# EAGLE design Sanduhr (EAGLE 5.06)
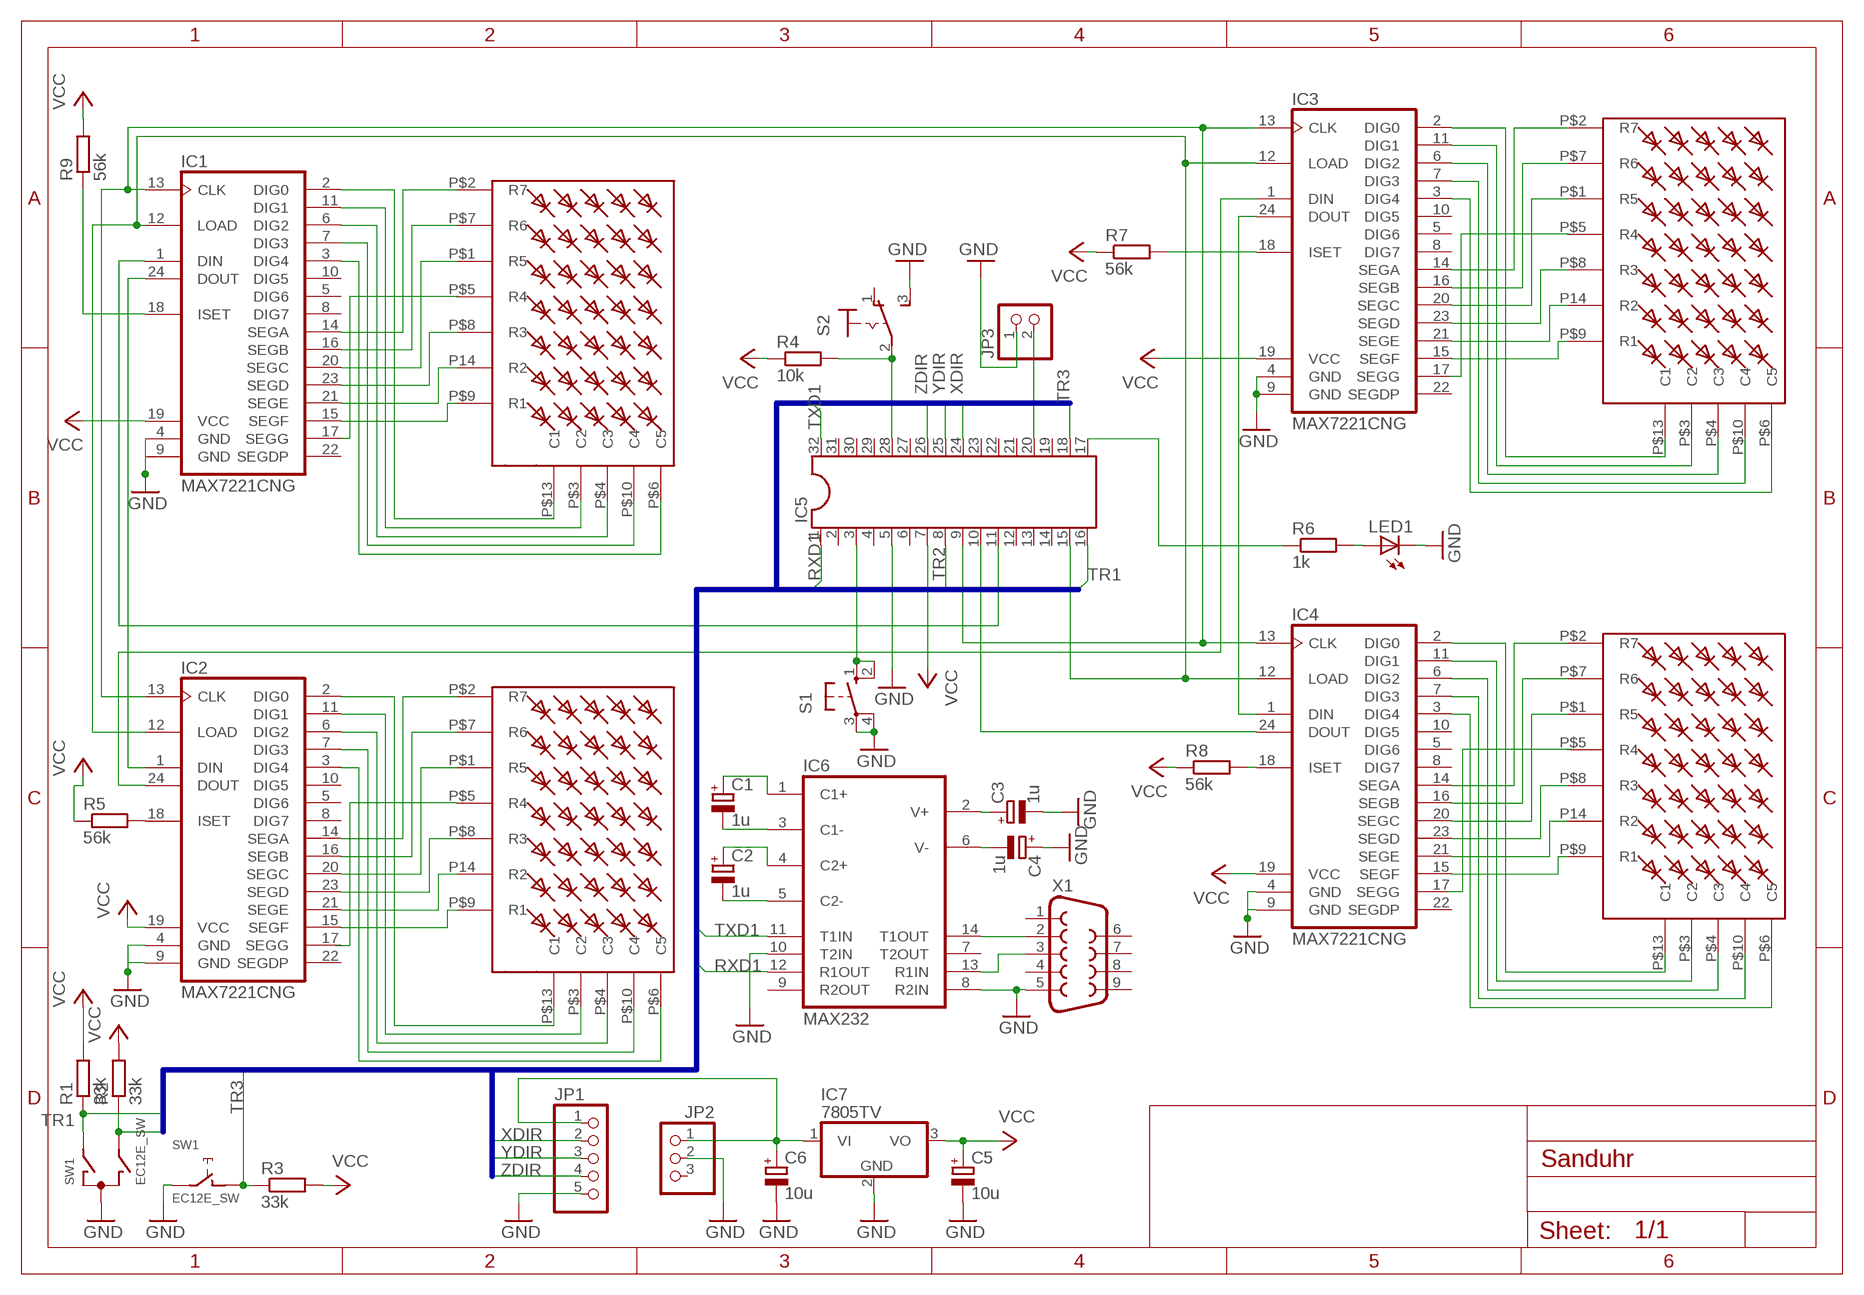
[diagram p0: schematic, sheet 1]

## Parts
C1  1u  CPOL-EUE2,5-6E  [E2,5-6E]
C2  1u  CPOL-EUE2,5-6E  [E2,5-6E]
C3  1u  CPOL-EUE2,5-6E  [E2,5-6E]
C4  1u  CPOL-EUE2,5-6E  [E2,5-6E]
C5  10u  CPOL-EUE2,5-6E  [E2,5-6E]
C6  10u  CPOL-EUE2,5-6E  [E2,5-6E]
IC1  MAX7221CNG  MAX7219CNG  [DIL24-3]
IC2  MAX7221CNG  MAX7219CNG  [DIL24-3]
IC3  MAX7221CNG  MAX7219CNG  [DIL24-3]
IC4  MAX7221CNG  MAX7219CNG  [DIL24-3]
IC5  DIL32  [DIL32]
IC6  MAX232  [DIL16]
IC7  7805TV  [TO220V]
JP1  PINHD-1X5  [1X05]
JP2  PINHD-1X3  [1X03]
JP3  PINHD-1X2  [1X02]
LED1  LED3MM  [LED3MM]
R1  33k  R-EU_0207/2V  [0207/2V]
R2  33k  R-EU_0207/2V  [0207/2V]
R3  33k  R-EU_0207/2V  [0207/2V]
R4  10k  R-EU_0207/2V  [0207/2V]
R5  56k  R-EU_0207/2V  [0207/2V]
R6  1k  R-EU_0207/2V  [0207/2V]
R7  56k  R-EU_0207/2V  [0207/2V]
R8  56k  R-EU_0207/2V  [0207/2V]
R9  56k  R-EU_0207/2V  [0207/2V]
S1  10-XX  [B3F-10XX]
S2  M9040P  [M9040P]
SW1  EC12E_SW  [ALPS_EC12E_SW]
U$1  TC20-11HWA  [P_SA20-11]
U$2  TC20-11HWA  [P_SA20-11]
U$3  TC20-11HWA  [P_SA20-11]
U$4  TC20-11HWA  [P_SA20-11]
X1  F09V  [F09V]

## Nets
GND: C3.- C4.+ C5.- C6.- IC1.4(GND) IC1.9(GND) IC2.4(GND) IC2.9(GND) IC3.4(GND) IC3.9(GND) IC4.4(GND) IC4.9(GND) IC5.5 IC6.8(R2IN) IC6.10(T2IN) IC7.2(GND) JP1.5 JP2.2 JP3.1 LED1.K(C) S1.3(P) S1.4(P1) S2.3(S) SW1.C SW1.E X1.5
N$1: IC1.14(SEGA) U$1.P$2(R7)
N$2: IC1.16(SEGB) U$1.P$7(R6)
N$3: IC1.20(SEGC) U$1.P$1(R5)
N$4: IC1.23(SEGD) U$1.P$8(R3)
N$5: IC1.21(SEGE) U$1.P14(R2)
N$6: IC1.15(SEGF) U$1.P$9(R1)
N$7: IC1.2(DIG0) U$1.P$13(C1)
N$8: IC1.11(DIG1) U$1.P$3(C2)
N$9: IC1.6(DIG2) U$1.P$4(C3)
N$10: IC1.7(DIG3) U$1.P$10(C4)
N$11: IC1.3(DIG4) U$1.P$6(C5)
N$12: IC2.14(SEGA) U$2.P$2(R7)
N$13: IC2.16(SEGB) U$2.P$7(R6)
N$14: IC2.20(SEGC) U$2.P$1(R5)
N$15: IC2.23(SEGD) U$2.P$8(R3)
N$16: IC2.21(SEGE) U$2.P14(R2)
N$17: IC2.15(SEGF) U$2.P$9(R1)
N$18: IC2.2(DIG0) U$2.P$13(C1)
N$19: IC2.11(DIG1) U$2.P$3(C2)
N$20: IC2.6(DIG2) U$2.P$4(C3)
N$21: IC2.7(DIG3) U$2.P$10(C4)
N$22: IC2.3(DIG4) U$2.P$6(C5)
N$23: IC3.14(SEGA) U$3.P$2(R7)
N$24: IC3.16(SEGB) U$3.P$7(R6)
N$25: IC3.20(SEGC) U$3.P$1(R5)
N$26: IC3.23(SEGD) U$3.P$8(R3)
N$27: IC3.21(SEGE) U$3.P14(R2)
N$28: IC3.15(SEGF) U$3.P$9(R1)
N$29: IC3.2(DIG0) U$3.P$13(C1)
N$30: IC3.11(DIG1) U$3.P$3(C2)
N$31: IC3.6(DIG2) U$3.P$4(C3)
N$32: IC3.7(DIG3) U$3.P$10(C4)
N$33: IC3.3(DIG4) U$3.P$6(C5)
N$34: IC4.14(SEGA) U$4.P$2(R7)
N$35: IC4.16(SEGB) U$4.P$7(R6)
N$36: IC4.20(SEGC) U$4.P$1(R5)
N$37: IC4.23(SEGD) U$4.P$8(R3)
N$38: IC4.21(SEGE) U$4.P14(R2)
N$39: IC4.15(SEGF) U$4.P$9(R1)
N$40: IC4.2(DIG0) U$4.P$13(C1)
N$41: IC4.11(DIG1) U$4.P$3(C2)
N$42: IC4.6(DIG2) U$4.P$4(C3)
N$43: IC4.7(DIG3) U$4.P$10(C4)
N$44: IC4.3(DIG4) U$4.P$6(C5)
N$45: IC1.24(DOUT) IC2.1(DIN)
N$46: IC2.24(DOUT) IC3.1(DIN)
N$47: IC3.24(DOUT) IC4.1(DIN)
N$48: IC1.13(CLK) IC2.13(CLK) IC3.13(CLK) IC4.13(CLK) IC5.9
N$49: IC4.24(DOUT) IC5.10
N$50: IC1.1(DIN) IC5.11
N$51: IC1.12(LOAD) IC2.12(LOAD) IC3.12(LOAD) IC4.12(LOAD) IC5.15
N$52: IC5.28 R4.2 S2.2(P)
N$53: LED1.A R6.2
N$54: IC3.18(ISET) R7.2
N$55: C1.+ IC6.1(C1+)
N$56: C1.- IC6.3(C1-)
N$57: C2.+ IC6.4(C2+)
N$58: C2.- IC6.5(C2-)
N$59: C3.+ IC6.2(V+)
N$60: C4.- IC6.6(V-)
N$61: IC6.14(T1OUT) X1.2
N$62: IC6.13(R1IN) X1.3
N$63: C6.+ IC7.1(VI) JP1.1 JP2.1
N$64: IC2.18(ISET) R5.2
N$65: IC4.18(ISET) R8.2
N$66: IC1.18(ISET) R9.1
N$67: IC5.3 S1.1(S) S1.2(S1)
N$68: IC5.17 R6.1
N$69: IC5.20 JP3.2
N$70: IC1.17(SEGG)
N$71: U$2.P$5(R4)
RXD1: IC5.1 IC6.12(R1OUT)
TR1: IC5.16 R1.1 SW1.A
TR2: IC5.8 R2.1 SW1.B
TR3: IC5.18 R3.1 SW1.D
TXD1: IC5.32 IC6.11(T1IN)
VCC: C5.+ IC1.19(VCC) IC2.19(VCC) IC3.19(VCC) IC4.19(VCC) IC5.7 IC7.3(VO) R1.2 R2.2 R3.2 R4.1 R5.1 R7.1 R8.1 R9.2
XDIR: IC5.24 JP1.2
YDIR: IC5.25 JP1.3
ZDIR: IC5.26 JP1.4
Unconnected: IC1.5(DIG6) IC1.8(DIG7) IC1.10(DIG5) IC1.22(SEGDP) IC2.5(DIG6) IC2.8(DIG7) IC2.10(DIG5) IC2.17(SEGG) IC2.22(SEGDP) IC3.5(DIG6) IC3.8(DIG7) IC3.10(DIG5) IC3.17(SEGG) IC3.22(SEGDP) IC4.5(DIG6) IC4.8(DIG7) IC4.10(DIG5) IC4.17(SEGG) IC4.22(SEGDP) IC5.2 IC5.4 IC5.6 IC5.12 IC5.13 IC5.14 IC5.19 IC5.21 IC5.22 IC5.23 IC5.27 IC5.29 IC5.30 IC5.31 IC6.7(T2OUT) IC6.9(R2OUT) JP2.3 S2.1(O) SW1.GND1(G) SW1.GND2(G) U$1.P$5(R4) U$3.P$5(R4) U$4.P$5(R4) X1.1 X1.4 X1.6 X1.7 X1.8 X1.9

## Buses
BUS:RXD1,TXD1,TR1,TR2,TR3,XDIR,YDIR,ZDIR

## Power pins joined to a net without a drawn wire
GND: IC6.15(GND)
VCC: IC6.16(VCC)

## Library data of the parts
C1-C6 = rcl:CPOL-EU: POLARIZED CAPACITOR, European symbol
IC1-IC4 = maxim:MAX7219CNG: LED DISPLAY DRIVER
IC5 = ic-package:DIL32: Dual In Line
IC6 = maxim:MAX232: RS232 TRANSEIVER
IC7 = linear:78*: Positive VOLTAGE REGULATOR Source: http://cache.national.com/ds/LM/LM78L05.pdf http://www.fairchildsemi.com/ds/LM/LM7805.pdf
JP1 = pinhead:PINHD-1X5: PIN HEADER
JP2 = pinhead:PINHD-1X3: PIN HEADER
JP3 = pinhead:PINHD-1X2: PIN HEADER
LED1 = led:LED: LED
R1-R9 = rcl:R-EU_: RESISTOR, European symbol
S1 = switch-omron:10-XX: OMRON SWITCH
S2 = switch:M9040P: TOGGLE SWITCH Marquardt
SW1 = switch-alps:EC12E_SW: ALPS rotary Encoder EC12E series with switch
U$1-U$4 = display-kingbright-skl:TC20-11HWA: 50mm 5x7 DOT MATRIX DISPLAY
X1 = con-subd:F09: SUB-D

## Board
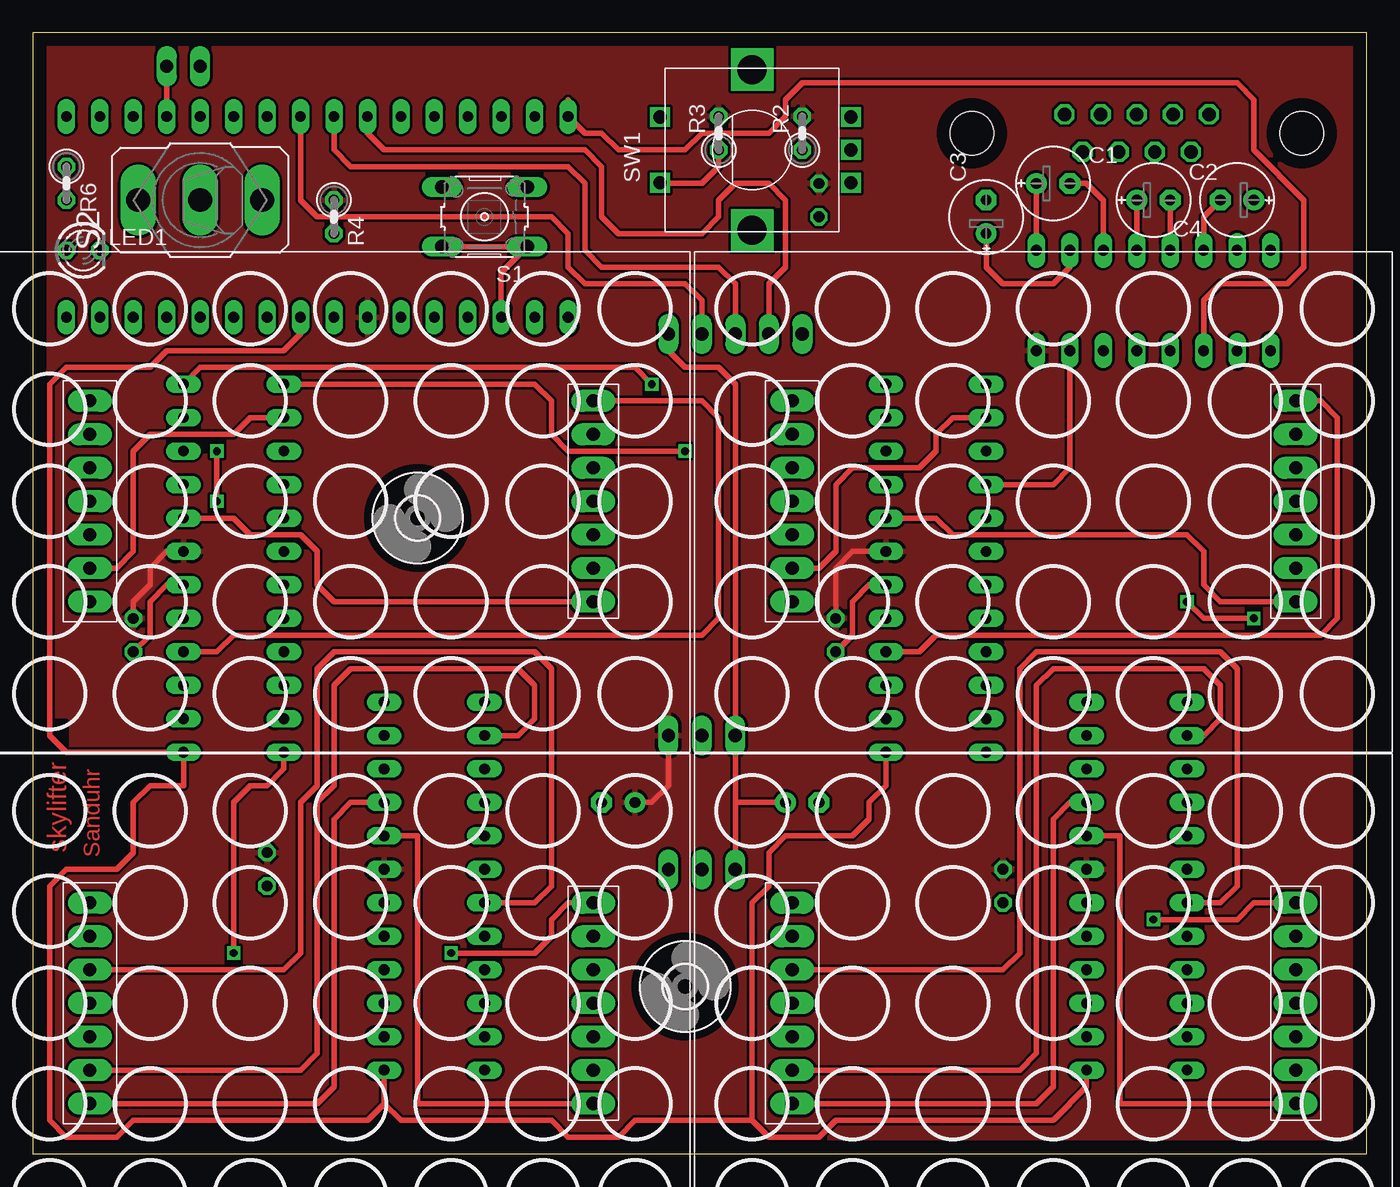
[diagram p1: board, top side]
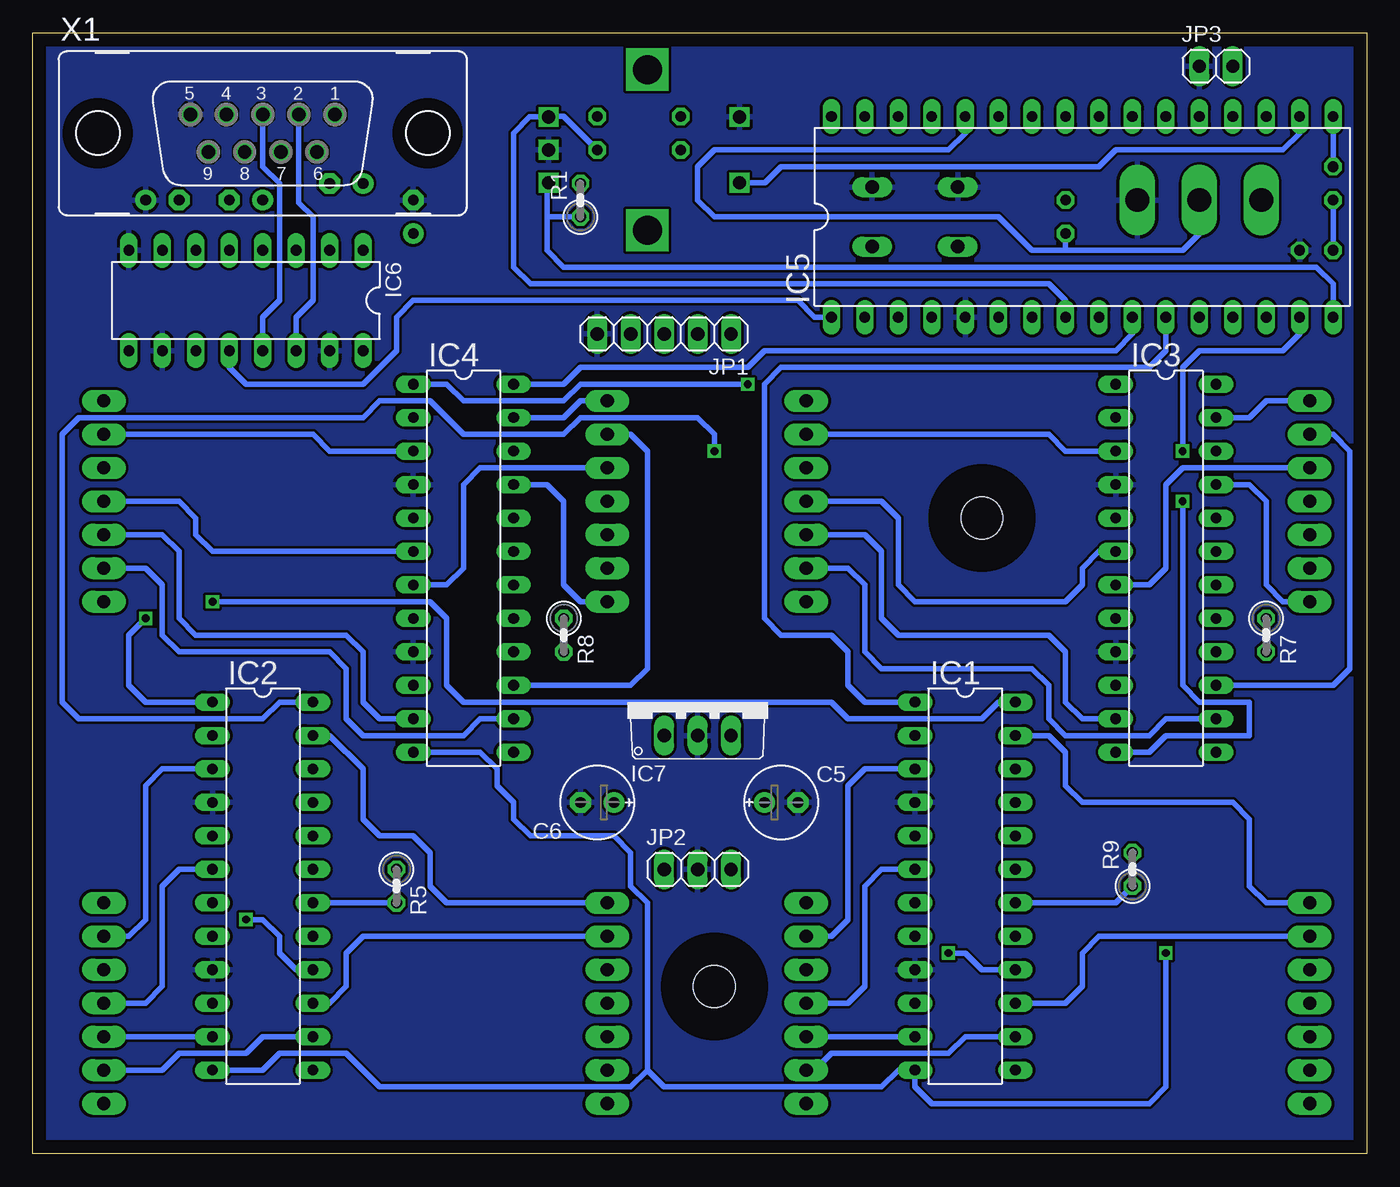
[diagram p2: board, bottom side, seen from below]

Size 101.27 x 85.08 mm. Coordinates in mm from the lower left corner, seen from the top.
Outline: 0,0 101.27,0 101.27,85.08 0,85.08 0,0
Copper layers (1*16): Top 0.035mm / dielectric 1.5mm / Bottom 0.035mm
Design rules "default": minimum track width 10mil, minimum drill 24mil, track to track 8mil, track to pad 8mil, pad to pad 8mil, via to via 8mil, smd to smd 8mil, copper to edge 40mil, drill to drill 8mil, minimum pad ring 10mil, minimum via ring 8mil, stop-mask expansion 4mil, vias tented up to drill 0mil, thermal gap 10mil

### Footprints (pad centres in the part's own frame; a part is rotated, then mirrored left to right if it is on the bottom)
E2,5-6E = drill 0.813 pad 1.575 round: + -1.27,0 | drill 0.813 pad 1.575 octagon: - 1.27,0
3,2 = hole 3.2: 0,0
DIL24-3 = drill 0.813 long: 1 -13.97,-3.81; 2 -11.43,-3.81; 3 -8.89,-3.81; 4 -6.35,-3.81; 5 -3.81,-3.81; 6 -1.27,-3.81; 7 1.27,-3.81; 8 3.81,-3.81; 9 6.35,-3.81; 10 8.89,-3.81; 11 11.43,-3.81; 12 13.97,-3.81; 13 13.97,3.81; 14 11.43,3.81; 15 8.89,3.81; 16 6.35,3.81; 17 3.81,3.81; 18 1.27,3.81; 19 -1.27,3.81; 20 -3.81,3.81; 21 -6.35,3.81; 22 -8.89,3.81; 23 -11.43,3.81; 24 -13.97,3.81
DIL32 = drill 0.813 long: 1 -19.05,-7.62; 2 -16.51,-7.62; 3 -13.97,-7.62; 4 -11.43,-7.62; 5 -8.89,-7.62; 6 -6.35,-7.62; 7 -3.81,-7.62; 8 -1.27,-7.62; 9 1.27,-7.62; 10 3.81,-7.62; 11 6.35,-7.62; 12 8.89,-7.62; 13 11.43,-7.62; 14 13.97,-7.62; 15 16.51,-7.62; 16 19.05,-7.62; 17 19.05,7.62; 18 16.51,7.62; 19 13.97,7.62; 20 11.43,7.62; 21 8.89,7.62; 22 6.35,7.62; 23 3.81,7.62; 24 1.27,7.62; 25 -1.27,7.62; 26 -3.81,7.62; 27 -6.35,7.62; 28 -8.89,7.62; 29 -11.43,7.62; 30 -13.97,7.62; 31 -16.51,7.62; 32 -19.05,7.62
DIL16 = drill 0.813 long: 1 -8.89,-3.81; 2 -6.35,-3.81; 3 -3.81,-3.81; 4 -1.27,-3.81; 5 1.27,-3.81; 6 3.81,-3.81; 7 6.35,-3.81; 8 8.89,-3.81; 9 8.89,3.81; 10 6.35,3.81; 11 3.81,3.81; 12 1.27,3.81; 13 -1.27,3.81; 14 -3.81,3.81; 15 -6.35,3.81; 16 -8.89,3.81
TO220V = drill 1.016 long: 1 -2.54,-2.54; 2 0,-2.54; 3 2.54,-2.54
1X05 = drill 1.016 long: 1 -5.08,0; 2 -2.54,0; 3 0,0; 4 2.54,0; 5 5.08,0
1X03 = drill 1.016 long: 1 -2.54,0; 2 0,0; 3 2.54,0
1X02 = drill 1.016 long: 1 -1.27,0; 2 1.27,0
LED3MM = drill 0.813 octagon: A -1.27,0; K 1.27,0
0207/2V = drill 0.813 octagon: 1 -1.27,0; 2 1.27,0
B3F-10XX = drill 1.016 long: 1 -3.251,2.261; 2 3.251,2.261; 3 -3.251,-2.261; 4 3.251,-2.261
M9040P = drill 1.803 long: 1 0,4.699; 2 0,0; 3 0,-4.699
ALPS_EC12E_SW = drill 1 square: A -2.5,-7.5; B 2.5,-7.5; C 0,-7.5; D -2.5,7; E 2.5,7 | drill 2.2 square: GND1 -6.1,0; GND2 6.1,0
P_SA20-11 = drill 1 pad 1.676 long: P14 -7.62,19.812; P$1 -7.62,-18.415; P$2 -5.08,-18.415; P$3 -2.54,-18.415; P$4 0,-18.415; P$5 2.54,-18.415; P$6 5.08,-18.415; P$7 7.62,-18.415; P$8 7.62,19.812; P$9 5.08,19.812; P$10 2.54,19.812; P$11 0,19.812; P$12 -2.54,19.812; P$13 -5.08,19.812
F09V = drill 1.016 octagon: 1 5.486,1.422; 2 2.743,1.422; 3 0,1.422; 4 -2.743,1.422; 5 -5.486,1.422; 6 4.115,-1.422; 7 1.372,-1.422; 8 -1.372,-1.422; 9 -4.115,-1.422 | hole 3.302: -12.522,0; 12.522,0

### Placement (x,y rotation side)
C1  77.47,73.66 0 top
C2  85.09,72.39 0 top
C3  72.39,71.12 90 top
C4  91.44,72.39 180 top
C5  44.45,26.67 0 bottom
C6  58.42,26.67 180 bottom
E$1  [3,2]  49.53,12.7 0 top
E$2  [3,2]  29.21,48.26 0 top
IC1  30.48,20.32 270 bottom
IC2  83.82,20.32 270 bottom
IC3  15.24,44.45 270 bottom
IC4  68.58,44.45 270 bottom
IC5  21.59,71.12 0 bottom
IC6  85.09,64.77 180 bottom
IC7  50.8,34.29 0 bottom
JP1  53.34,62.23 180 bottom
JP2  50.8,21.59 0 bottom
JP3  11.43,82.55 0 bottom
LED1  3.81,68.58 0 top
R1  59.69,72.39 90 bottom
R2  58.42,77.47 90 top
R3  52.07,77.47 90 top
R4  22.86,71.12 270 top
R5  73.66,20.32 270 bottom
R6  2.54,73.66 270 top
R7  7.62,39.37 270 bottom
R8  60.96,39.37 270 bottom
R9  17.78,21.59 90 bottom
S1  34.29,71.12 180 top
S2  12.7,72.39 90 top
SW1  54.61,76.2 90 top
U$1  24.13,11.43 90 top
U$2  77.47,11.43 90 top
U$3  24.13,49.53 90 top
U$4  77.47,49.53 90 top
X1  83.82,77.47 0 bottom

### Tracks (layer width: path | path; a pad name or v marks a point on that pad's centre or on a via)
GND
  Top 0.406: IC4.4 77.47,50.8 78.74,52.07 IC6.15
  pour Bottom: 0,85.09 101.6,85.09 101.6,0 0,0
N$1
  Bottom 0.406: U$1.P$2 41.91,6.35 40.64,7.62 31.75,7.62 30.48,8.89 IC1.14
N$2  (via drill 0.6)
  Top 0.406: U$1.P$7 40.64,19.05 39.37,17.78 39.37,16.51 38.1,15.24 v31.75,15.24
  Bottom 0.406: v31.75,15.24 30.48,15.24 29.21,13.97 IC1.16
N$3
  Top 0.406: U$1.P$1 29.21,3.81 29.21,24.13 IC1.20
N$4
  Bottom 0.406: U$1.P$8 7.62,19.05 8.89,20.32 8.89,25.4 10.16,26.67 21.59,26.67 22.86,27.94 22.86,30.48 24.13,31.75 IC1.23
N$5
  Top 0.406: IC1.21 24.13,26.67 22.86,25.4 22.86,5.08 21.59,3.81 U$1.P14
N$6
  Bottom 0.406: IC1.15 22.86,11.43 21.59,12.7 21.59,15.24 20.32,16.51 U$1.P$9
N$7
  Top 0.406: IC1.2 36.83,31.75 38.1,33.02 38.1,35.56 36.83,36.83 24.13,36.83 22.86,35.56 22.86,27.94 21.59,26.67 21.59,7.62 20.32,6.35 U$1.P$13
N$8
  Bottom 0.406: IC1.11 U$1.P$3
N$9
  Bottom 0.406: U$1.P$4 39.37,11.43 38.1,12.7 38.1,20.32 36.83,21.59 IC1.6
N$10
  Top 0.406: U$1.P$10 19.05,13.97 20.32,15.24 20.32,26.67 21.59,27.94 21.59,36.83 22.86,38.1 38.1,38.1 39.37,36.83 39.37,20.32 38.1,19.05 IC1.7
  Bottom 0.406: U$1.P$10 5.08,13.97
N$11
  Bottom 0.406: U$1.P$6 40.64,16.51 39.37,17.78 39.37,27.94 38.1,29.21 IC1.3
N$12
  Bottom 0.406: 96.52,6.35 U$2.P$2 91.44,6.35 90.17,7.62 85.09,7.62 83.82,8.89 IC2.14
N$13  (via drill 0.6)
  Top 0.406: U$2.P$7 92.71,19.05 91.44,17.78 v85.09,17.78
  Bottom 0.406: v85.09,17.78 83.82,17.78 82.55,16.51 82.55,15.24 81.28,13.97 IC2.16
N$14
  Top 0.406: U$2.P$1 82.55,3.81 82.55,24.13 IC2.20
N$15
  Bottom 0.406: IC2.23 78.74,31.75 76.2,29.21 76.2,25.4 74.93,24.13 72.39,24.13 71.12,22.86 71.12,20.32 69.85,19.05 U$2.P$8
N$16
  Top 0.406: U$2.P14 76.2,3.81 77.47,5.08 77.47,25.4 78.74,26.67 IC2.21
N$17
  Bottom 0.406: U$2.P$9 76.2,16.51 77.47,15.24 77.47,12.7 78.74,11.43 IC2.15
N$18
  Top 0.406: U$2.P$13 74.93,6.35 76.2,7.62 76.2,35.56 77.47,36.83 88.9,36.83 90.17,35.56 90.17,33.02 88.9,31.75 IC2.2
N$19
  Bottom 0.406: IC2.11 U$2.P$3
N$20
  Bottom 0.406: U$2.P$4 92.71,11.43 91.44,12.7 91.44,20.32 90.17,21.59 IC2.6
N$21
  Top 0.406: U$2.P$10 73.66,13.97 74.93,15.24 74.93,36.83 76.2,38.1 90.17,38.1 91.44,36.83 91.44,20.32 90.17,19.05 IC2.7
N$22
  Bottom 0.406: U$2.P$6 93.98,16.51 92.71,17.78 92.71,27.94 91.44,29.21 IC2.3
N$23
  Bottom 0.406: U$3.P$2 39.37,44.45 38.1,43.18 38.1,38.1 36.83,36.83 25.4,36.83 24.13,35.56 24.13,33.02 22.86,31.75 16.51,31.75 15.24,33.02 IC3.14
N$24
  Top 0.406: U$3.P$7 50.8,57.15 52.07,55.88 52.07,40.64 50.8,39.37 15.24,39.37 13.97,38.1 IC3.16
N$25
  Top 0.406: U$3.P$1 36.83,41.91 22.86,41.91 21.59,43.18 21.59,45.72 20.32,46.99 16.51,46.99 15.24,48.26 IC3.20
N$26
  Bottom 0.406: IC3.23 8.89,55.88 7.62,57.15 U$3.P$8
N$27
  Bottom 0.406: IC3.21 8.89,50.8 7.62,49.53 7.62,43.18 6.35,41.91 U$3.P14
N$28
  Bottom 0.406: IC3.15 2.54,35.56 1.27,36.83 1.27,53.34 2.54,54.61 U$3.P$9
N$29
  Top 0.406: U$3.P$13 6.35,44.45 7.62,45.72 7.62,53.34 8.89,54.61 15.24,54.61 16.51,55.88 IC3.2
N$30
  Bottom 0.406: 43.18,46.99 U$3.P$3 38.1,46.99 36.83,45.72 36.83,40.64 35.56,39.37 24.13,39.37 22.86,38.1 22.86,34.29 21.59,33.02 IC3.11
N$31
  Bottom 0.406: U$3.P$4 36.83,49.53 35.56,48.26 35.56,43.18 34.29,41.91 22.86,41.91 21.59,43.18 21.59,44.45 20.32,45.72 IC3.6
N$32
  Bottom 0.406: U$3.P$10 13.97,52.07 15.24,50.8 15.24,44.45 16.51,43.18 IC3.7
N$33
  Bottom 0.406: U$3.P$6 24.13,54.61 22.86,53.34 IC3.3
N$34
  Bottom 0.406: U$4.P$2 92.71,44.45 91.44,43.18 91.44,39.37 90.17,38.1 78.74,38.1 77.47,36.83 77.47,33.02 76.2,31.75 68.58,31.75 67.31,33.02 IC4.14
N$35
  Top 0.406: U$4.P$7 97.79,57.15 99.06,55.88 99.06,40.64 97.79,39.37 68.58,39.37 67.31,38.1 IC4.16
N$36
  Top 0.406: U$4.P$1 90.17,41.91 88.9,43.18 88.9,45.72 87.63,46.99 69.85,46.99 68.58,48.26 IC4.20
N$37
  Bottom 0.406: IC4.23 60.96,55.88 59.69,57.15 U$4.P$8
N$38
  Bottom 0.406: U$4.P14 59.69,41.91 60.96,43.18 60.96,49.53 62.23,50.8 IC4.21
N$39
  Bottom 0.406: U$4.P$9 55.88,54.61 54.61,53.34 54.61,36.83 55.88,35.56 IC4.15
N$40
  Top 0.406: IC4.2 69.85,55.88 68.58,54.61 68.58,53.34 67.31,52.07 62.23,52.07 60.96,50.8 60.96,45.72 59.69,44.45 U$4.P$13
N$41
  Bottom 0.406: U$4.P$3 91.44,46.99 90.17,45.72 90.17,40.64 88.9,39.37 77.47,39.37 76.2,38.1 76.2,34.29 74.93,33.02 IC4.11
N$42
  Bottom 0.406: U$4.P$4 90.17,49.53 88.9,48.26 88.9,46.99 87.63,45.72 IC4.6
N$43
  Bottom 0.406: U$4.P$10 67.31,52.07 68.58,50.8 68.58,44.45 69.85,43.18 IC4.7
N$44
  Bottom 0.406: U$4.P$6 80.01,54.61 78.74,53.34 IC4.3
N$45  (via drill 0.6)
  Top 0.406: v92.71,40.64 88.9,40.64 v87.63,41.91
  Bottom 0.406: IC1.24 27.94,34.29 29.21,33.02 39.37,33.02 40.64,34.29 68.58,34.29 69.85,35.56 69.85,40.64 71.12,41.91 v87.63,41.91 | IC2.1 92.71,34.29 93.98,35.56 93.98,39.37 v92.71,40.64
N$46  (via drill 0.6)
  Top 0.406: v49.53,53.34 40.64,53.34 39.37,54.61 39.37,57.15 38.1,58.42 IC3.1
  Bottom 0.406: IC2.24 82.55,34.29 83.82,33.02 97.79,33.02 99.06,34.29 99.06,54.61 97.79,55.88 76.2,55.88 74.93,57.15 71.12,57.15 68.58,54.61 60.96,54.61 59.69,55.88 50.8,55.88 49.53,54.61 v49.53,53.34
N$47  (via drill 0.6)
  Top 0.406: IC3.24 12.7,59.69 45.72,59.69 v46.99,58.42
  Bottom 0.406: IC4.1 69.85,58.42 68.58,57.15 60.96,57.15 59.69,58.42 v46.99,58.42
N$48
  Top 0.406: IC2.13 80.01,5.08 77.47,2.54 60.96,2.54 59.69,1.27 55.88,1.27 54.61,2.54 | 54.61,2.54 45.72,2.54 44.45,1.27 40.64,1.27 39.37,2.54 27.94,2.54 26.67,3.81 | IC4.13 64.77,27.94 63.5,26.67 63.5,25.4 62.23,24.13 57.15,24.13 55.88,22.86 55.88,20.32 54.61,19.05 54.61,2.54 | 26.67,3.81 IC1.13 | 26.67,3.81 25.4,2.54 7.62,2.54 6.35,1.27 2.54,1.27 1.27,2.54 1.27,20.32 2.54,21.59 6.35,21.59 7.62,22.86 7.62,26.67 8.89,27.94 11.43,27.94 IC3.13 2.54,30.48 1.27,31.75 1.27,58.42 2.54,59.69 8.89,59.69 10.16,60.96 19.05,60.96 20.32,62.23 IC5.9
N$49
  Bottom 0.406: IC4.24 60.96,58.42 59.69,59.69 46.99,59.69 45.72,60.96 19.05,60.96 17.78,62.23 IC5.10
N$50
  Bottom 0.406: IC1.1 38.1,34.29 39.37,35.56 39.37,38.1 40.64,39.37 44.45,39.37 45.72,40.64 45.72,58.42 44.45,59.69 16.51,59.69 15.24,60.96 IC5.11
N$51  (via drill 0.6)
  Top 0.406: IC3.12 19.05,29.21 17.78,27.94 16.51,27.94 15.24,26.67 v15.24,15.24 | v13.97,49.53 v13.97,53.34
  Bottom 0.406: IC2.12 83.82,6.35 82.55,7.62 77.47,7.62 74.93,5.08 55.88,5.08 54.61,6.35 | IC4.12 67.31,30.48 66.04,29.21 66.04,27.94 64.77,26.67 64.77,25.4 63.5,24.13 57.15,24.13 55.88,22.86 55.88,20.32 54.61,19.05 54.61,6.35 | v15.24,15.24 15.24,5.08 16.51,3.81 33.02,3.81 34.29,5.08 IC1.12 35.56,6.35 36.83,5.08 53.34,5.08 54.61,6.35 | IC3.12 16.51,30.48 15.24,31.75 8.89,31.75 8.89,34.29 12.7,34.29 13.97,35.56 v13.97,49.53 | v13.97,53.34 13.97,59.69 12.7,60.96 6.35,60.96 5.08,62.23 IC5.15
N$52
  Bottom 0.406: S2.2 12.7,69.85 13.97,68.58 22.86,68.58 | 22.86,68.58 25.4,68.58 27.94,71.12 49.53,71.12 50.8,72.39 50.8,74.93 49.53,76.2 31.75,76.2 30.48,77.47 IC5.28 | 22.86,68.58 R4.2
N$53
  Bottom 0.406: LED1.A R6.2
N$54
  Top 0.406: IC3.18 10.16,43.18 8.89,41.91 8.89,39.37 R7.2
N$55
  Top 0.406: IC6.1 C1.+
N$56
  Top 0.406: C1.- 80.01,73.66 81.28,72.39 IC6.3
N$57
  Top 0.406: IC6.4 C2.+
N$58
  Top 0.406: IC6.5 C2.-
N$59
  Top 0.406: IC6.2 78.74,67.31 77.47,66.04 73.66,66.04 72.39,67.31 C3.+
N$60
  Top 0.406: IC6.6 88.9,71.12 C4.-
N$61
  Bottom 0.406: X1.2 81.08,72.19 80.01,71.12 80.01,64.77 81.28,63.5 IC6.14
N$62
  Bottom 0.406: X1.3 83.82,74.93 82.55,73.66 82.55,64.77 83.82,63.5 IC6.13
N$63
  Top 0.406: JP2.1 53.34,26.67 | 53.34,26.67 IC7.1 53.34,58.42 52.07,59.69 49.53,59.69 48.26,60.96 JP1.1 | 53.34,26.67 C6.+
N$64
  Bottom 0.406: R5.2 IC2.18
N$65
  Top 0.406: IC4.18 63.5,43.18 62.23,41.91 62.23,39.37 R8.2
N$66
  Bottom 0.406: IC1.18 19.05,19.05 R9.1
N$67
  Top 0.406: IC5.3 35.56,66.88 37.05,68.36 | 37.05,68.36 S1.1 | S1.2 36.55,68.86 37.05,68.36
N$68
  Bottom 0.406: R6.1 IC5.17
N$69
  Top 0.406: IC5.20 JP3.2
RXD1
  Bottom 0.406: IC5.1 41.91,63.5 43.18,64.77 72.39,64.77 73.66,63.5 73.66,60.96 76.2,58.42 85.09,58.42 86.36,59.69 IC6.12
TR1
  Bottom 0.406: SW1.A 62.19,73.7 62.23,73.66 62.23,71.12 | 62.23,71.12 62.23,68.58 60.96,67.31 3.81,67.31 2.54,66.04 IC5.16 | 62.23,71.12 R1.1
TR2
  Bottom 0.406: IC5.8 22.86,64.77 24.13,66.04 63.5,66.04 64.77,67.31 64.77,77.47 63.54,78.7 SW1.B 62.07,78.74 60.96,78.74 R2.1
TR3
  Top 0.406: R3.1 52.07,74.93 50.8,73.66 47.65,73.66 SW1.D
  Bottom 0.406: SW1.D 45.68,73.7 44.45,74.93 20.32,74.93 19.05,76.2 6.35,76.2 5.08,77.47 IC5.18
TXD1
  Top 0.406: 40.64,80.01 IC5.32 41.91,77.47 43.18,77.47 44.45,76.2 49.53,76.2 50.8,77.47 55.88,77.47 57.15,78.74 57.15,80.01 58.42,81.28 91.44,81.28 92.71,80.01 92.71,76.2 96.52,72.39 96.52,67.31 95.25,66.04 90.17,66.04 88.9,64.77 IC6.11
VCC
  Top 0.406: C5.+ 46.99,26.67 48.26,27.94 IC7.3 | R7.1 7.62,41.91 8.89,43.18 8.89,44.45 10.16,45.72 IC3.19 | IC4.19 62.23,45.72 60.96,44.45 R8.1
  pour Top: 0,85.09 101.6,85.09 101.6,0 0,0
XDIR
  Top 0.406: JP1.2 50.8,64.77 49.53,66.04 41.91,66.04 40.64,67.31 40.64,69.85 39.37,71.12 21.59,71.12 20.32,72.39 IC5.24
YDIR
  Top 0.406: JP1.3 53.34,66.04 52.07,67.31 43.18,67.31 41.91,68.58 41.91,73.66 40.64,74.93 24.13,74.93 22.86,76.2 IC5.25
ZDIR
  Top 0.406: JP1.4 55.88,66.04 57.15,67.31 57.15,72.39 55.88,73.66 53.34,73.66 52.07,72.39 52.07,71.12 50.8,69.85 44.45,69.85 43.18,71.12 43.18,74.93 41.91,76.2 26.67,76.2 25.4,77.47 IC5.26

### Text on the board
Top: Sanduhr | skylifter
